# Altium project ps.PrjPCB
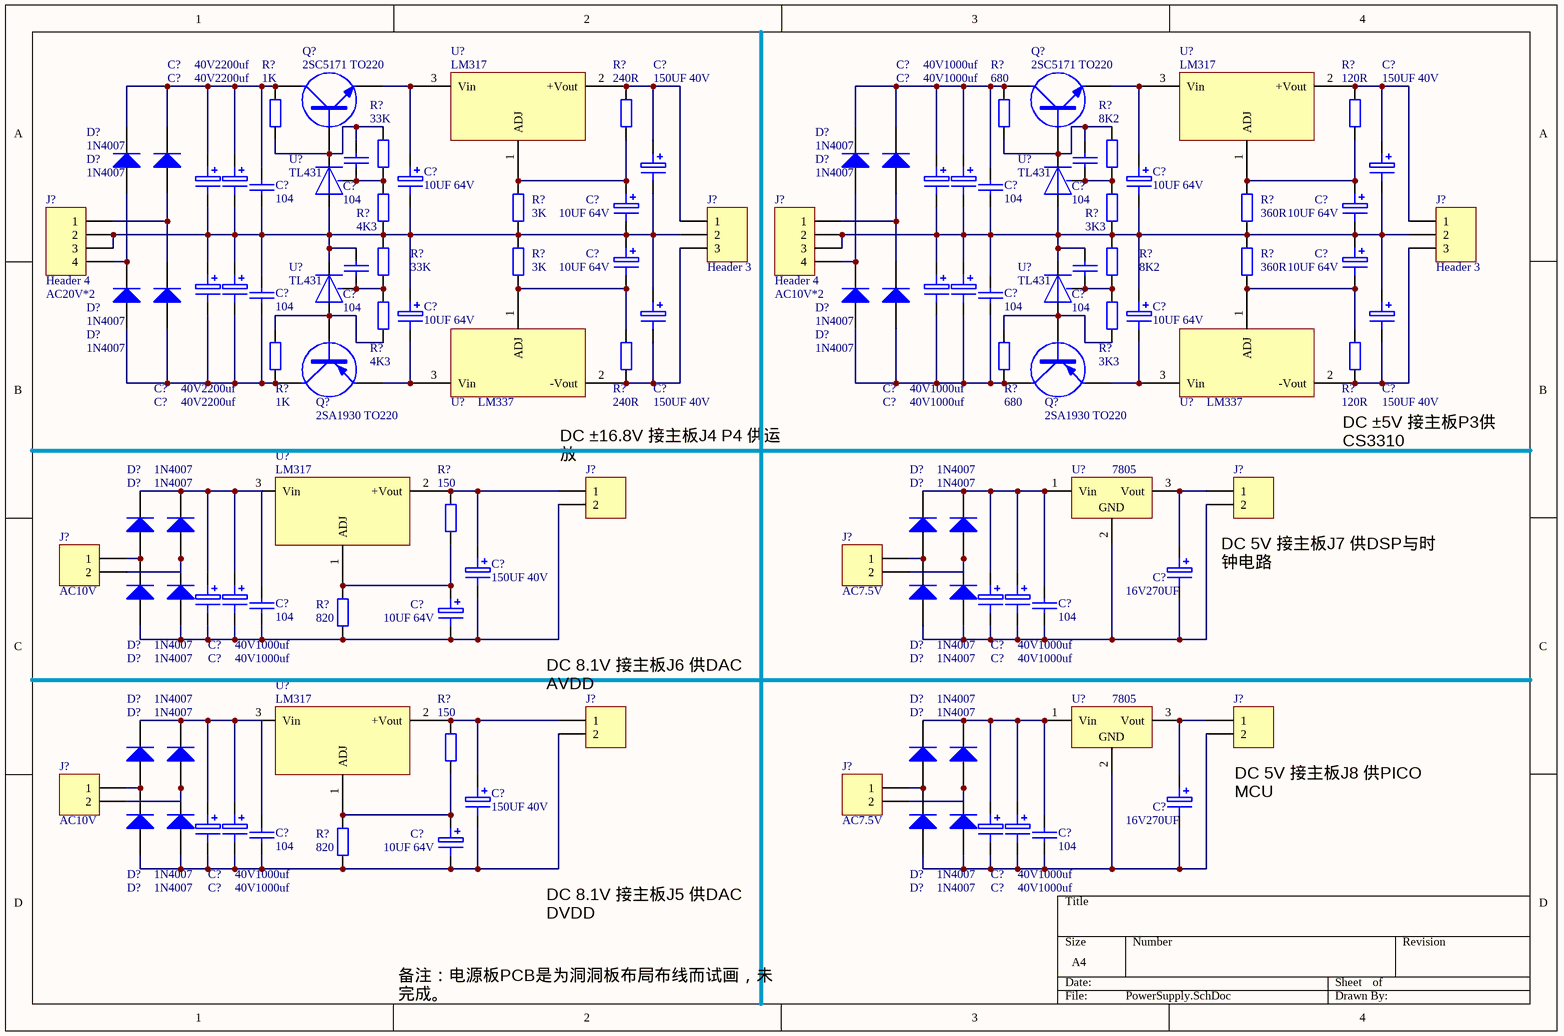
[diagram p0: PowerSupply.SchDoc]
1 sheet, 122 parts. Net scope: global (net labels, ports and power ports of the same name join across sheets).
Board file: ps.PcbDoc

## Sheet PowerSupply.SchDoc
size A4

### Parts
(Parts that share a designator on the sheet are numbered #1, #2 ... from top to bottom, then left to right.)
C1  104  [RAD0.2C]
C2  150UF 40V  [PEG124_D]
C3  40V2200uf  [PEG124_J]
C4  40V2200uf  [PEG124_J]
C5  10UF 64V  [PEG124_A]
C6  104  [RAD0.2C]
C7  10UF 64V  [PEG124_A]
C8  10UF 64V  [PEG124_A]
C9  104  [RAD0.2C]
C10  40V2200uf  [PEG124_J]
C11  40V2200uf  [PEG124_J]
C12  104  [RAD0.2C]
C13  10UF 64V  [PEG124_A]
C14  150UF 40V  [PEG124_D]
C18  150UF 40V  [RB.2/.4s]
C19  40V1000uf  [PEG124_S.7]
C20  104  [RAD0.2C]
C21  10UF 64V  [RB.1/.2C]
C?#1  104  [RAD0.2C]
C?#2  150UF 40V  [PEG124_D]
C?#3  40V1000uf  [PEG124_J]
C?#4  40V1000uf  [PEG124_J]
C?#5  10UF 64V  [PEG124_A]
C?#6  104  [RAD0.2C]
C?#7  10UF 64V  [PEG124_A]
C?#8  10UF 64V  [PEG124_A]
C?#9  40V1000uf  [PEG124_J]
C?#10  40V1000uf  [PEG124_J]
C?#11  104  [RAD0.2C]
C?#12  104  [RAD0.2C]
C?#13  10UF 64V  [PEG124_A]
C?#14  150UF 40V  [PEG124_D]
C?#15  16V270UF  [RB.2/.4s]
C?#16  40V1000uf  [PEG124_S.7]
C?#17  40V1000uf  [PEG124_S.7]
C?#18  40V1000uf  [PEG124_S.7]
C?#19  104  [RAD0.2C]
C?#20  150UF 40V  [RB.2/.4s]
C?#21  16V270UF  [RB.2/.4s]
C?#22  40V1000uf  [PEG124_S.7]
C?#23  40V1000uf  [PEG124_S.7]
C?#24  40V1000uf  [PEG124_S.7]
C?#25  40V1000uf  [PEG124_S.7]
C?#26  104  [RAD0.2C]
C?#27  10UF 64V  [RB.1/.2C]
C?#28  104  [RAD0.2C]
D1  1N4007  [DO-41]
D2  1N4007  [DO-41]
D3  1N4007  [DO-41]
D4  1N4007  [DO-41]
D9  1N4007  [DO-41]
D10  1N4007  [DO-41]
D11  1N4007  [DO-41]
D12  1N4007  [DO-41]
D?#1  1N4007  [DO-41]
D?#2  1N4007  [DO-41]
D?#3  1N4007  [DO-41]
D?#4  1N4007  [DO-41]
D?#5  1N4007  [DO-41]
D?#6  1N4007  [DO-41]
D?#7  1N4007  [DO-41]
D?#8  1N4007  [DO-41]
D?#9  1N4007  [DO-41]
D?#10  1N4007  [DO-41]
D?#11  1N4007  [DO-41]
D?#12  1N4007  [DO-41]
D?#13  1N4007  [DO-41]
D?#14  1N4007  [DO-41]
D?#15  1N4007  [DO-41]
D?#16  1N4007  [DO-41]
J1  Header 4  [HDR1X4]
J2  Header 3  [HDR1X3]
J5  (no value)  [SIP2C]
J6  (no value)  [SIP2C]
J?#1  Header 4  [HDR1X4]
J?#2  Header 3  [HDR1X3]
J?#3  (no value)  [SIP2C]
J?#4  (no value)  [SIP2C]
J?#5  (no value)  [SIP2C]
J?#6  (no value)  [SIP2C]
J?#7  (no value)  [SIP2C]
J?#8  (no value)  [SIP2C]
Q1  2SC5171 TO220  [TO-220S]
Q2  2SA1930 TO220  [TO-220s]
Q?#1  2SC5171 TO220  [TO-220S]
Q?#2  2SA1930 TO220  [TO-220s]
R1  1K  [AXIAL-0.4]
R2  240R  [AXIAL-0.4]
R3  33K  [AXIAL-0.4]
R4  4K3  [AXIAL-0.4]
R5  3K  [AXIAL-0.4]
R6  33K  [AXIAL-0.4]
R7  3K  [AXIAL-0.4]
R8  1K  [AXIAL-0.4]
R9  4K3  [AXIAL-0.4]
R10  240R  [AXIAL-0.4]
R11  150  [AXIAL-0.4]
R12  820  [AXIAL-0.4]
R?#1  680  [AXIAL-0.4]
R?#2  120R  [AXIAL-0.4]
R?#3  8K2  [AXIAL-0.4]
R?#4  3K3  [AXIAL-0.4]
R?#5  360R  [AXIAL-0.4]
R?#6  8K2  [AXIAL-0.4]
R?#7  360R  [AXIAL-0.4]
R?#8  3K3  [AXIAL-0.4]
R?#9  680  [AXIAL-0.4]
R?#10  120R  [AXIAL-0.4]
R?#11  150  [AXIAL-0.4]
R?#12  820  [AXIAL-0.4]
U1  LM317  [TO-220s]
U2  TL431  [to-92c]
U3  TL431  [to-92c]
U4  LM337  [TO-220s]
U6  LM317  [TO-220sh]
U?#1  LM317  [TO-220s]
U?#2  TL431  [to-92c]
U?#3  TL431  [to-92c]
U?#4  LM337  [TO-220s]
U?#5  7805  [TO-220s]
U?#6  LM317  [TO-220sh]
U?#7  7805  [TO-220s]

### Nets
NetC1_1: C1.1 Q1.1(B) R1.1 R3.1 U2.3(K)
NetC1_2: C1.2 R3.2 R4.2 U2.1(REF)
NetC2_1: C2.1 J2.1 R2.2 U1.2(+Vout)
NetC2_2: C2.2 C3.2 C4.2 C5.2 C6.2 C7.2 C8.1 C9.2 C10.1 C11.1 C12.1 C13.1 C14.1 J1.2 J1.3 J2.2 R4.1 R5.1 R6.2 R7.2 U2.2(A) U3.3(K)
NetC3_1: C3.1 C4.1 C6.1 D1.2(K) D2.2(K) Q1.2(C) R1.2
NetC5_1: C5.1 Q1.3(E) U1.3(Vin)
NetC7_1: C7.1 R2.1 R5.2 U1.1(ADJ)
NetC8_2: C8.2 R7.1 R10.2 U4.1(ADJ)
NetC9_1: C9.1 R6.1 R9.2 U3.1(REF)
NetC10_2: C10.2 C11.2 C12.2 D3.1(A) D4.1(A) Q2.3(C) R8.1
NetC13_2: C13.2 Q2.2(E) U4.3(Vin)
NetC14_2: C14.2 J2.3 R10.1 U4.2(-Vout)
NetC18_1: C18.1 J5.1 R11.2 U6.2(+Vout)
NetC18_2: C18.2 C19.2 C20.2 C21.2 C?#16.2 D11.1(A) D12.1(A) J5.2 R12.1
NetC19_1: C19.1 C20.1 C?#16.1 D9.2(K) D10.2(K) U6.3(Vin)
NetC21_1: C21.1 R11.1 R12.2 U6.1(ADJ)
NetC?#1_1: C?#1.1 Q?#1.1(B) R?#1.1 R?#3.1 U?#2.3(K)
NetC?#1_2: C?#1.2 R?#3.2 R?#4.2 U?#2.1(REF)
NetC?#2_1: C?#2.1 J?#2.1 R?#2.2 U?#1.2(+Vout)
NetC?#2_2: C?#2.2 C?#3.2 C?#4.2 C?#5.2 C?#6.2 C?#7.2 C?#8.1 C?#9.1 C?#10.1 C?#11.2 C?#12.1 C?#13.1 C?#14.1 J?#1.2 J?#1.3 J?#2.2 R?#4.1 R?#5.1 R?#6.2 R?#7.2 U?#2.2(A) U?#3.3(K)
NetC?#3_1: C?#3.1 C?#4.1 C?#6.1 D?#1.2(K) D?#2.2(K) Q?#1.2(C) R?#1.2
NetC?#5_1: C?#5.1 Q?#1.3(E) U?#1.3(Vin)
NetC?#7_1: C?#7.1 R?#2.1 R?#5.2 U?#1.1(ADJ)
NetC?#8_2: C?#8.2 R?#7.1 R?#10.2 U?#4.1(ADJ)
NetC?#9_2: C?#9.2 C?#10.2 C?#12.2 D?#3.1(A) D?#4.1(A) Q?#2.3(C) R?#9.1
NetC?#11_1: C?#11.1 R?#6.1 R?#8.2 U?#3.1(REF)
NetC?#13_2: C?#13.2 Q?#2.2(E) U?#4.3(Vin)
NetC?#14_2: C?#14.2 J?#2.3 R?#10.1 U?#4.2(-Vout)
NetC?#15_1: C?#15.1 J?#3.1 U?#5.3(Vout)
NetC?#15_2: C?#15.2 C?#17.2 C?#18.2 C?#19.2 D?#7.1(A) D?#8.1(A) J?#3.2 U?#5.2(GND)
NetC?#17_1: C?#17.1 C?#18.1 C?#19.1 D?#5.2(K) D?#6.2(K) U?#5.1(Vin)
NetC?#20_1: C?#20.1 J?#5.1 R?#11.2 U?#6.2(+Vout)
NetC?#20_2: C?#20.2 C?#22.2 C?#23.2 C?#26.2 C?#27.2 D?#13.1(A) D?#14.1(A) J?#5.2 R?#12.1
NetC?#21_1: C?#21.1 J?#6.1 U?#7.3(Vout)
NetC?#21_2: C?#21.2 C?#24.2 C?#25.2 C?#28.2 D?#15.1(A) D?#16.1(A) J?#6.2 U?#7.2(GND)
NetC?#22_1: C?#22.1 C?#23.1 C?#26.1 D?#9.2(K) D?#10.2(K) U?#6.3(Vin)
NetC?#24_1: C?#24.1 C?#25.1 C?#28.1 D?#11.2(K) D?#12.2(K) U?#7.1(Vin)
NetC?#27_1: C?#27.1 R?#11.1 R?#12.2 U?#6.1(ADJ)
NetD1_1: D1.1(A) D3.2(K) J1.4
NetD2_1: D2.1(A) D4.2(K) J1.1
NetD9_1: D9.1(A) D11.2(K) J6.1
NetD10_1: D10.1(A) D12.2(K) J6.2
NetD?#1_1: D?#1.1(A) D?#3.2(K) J?#1.4
NetD?#2_1: D?#2.1(A) D?#4.2(K) J?#1.1
NetD?#5_1: D?#5.1(A) D?#7.2(K) J?#4.1
NetD?#6_1: D?#6.1(A) D?#8.2(K) J?#4.2
NetD?#9_1: D?#9.1(A) D?#13.2(K) J?#7.1
NetD?#10_1: D?#10.1(A) D?#14.2(K) J?#7.2
NetD?#11_1: D?#11.1(A) D?#15.2(K) J?#8.1
NetD?#12_1: D?#12.1(A) D?#16.2(K) J?#8.2
NetQ2_1: Q2.1(B) R8.2 R9.1 U3.2(A)
NetQ?#2_1: Q?#2.1(B) R?#8.1 R?#9.2 U?#3.2(A)

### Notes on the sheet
- AC20V*2
- AC10V*2
- (near J5) DC ±16.8V 接主板J4 P4 供运放
- DC ±5V 接主板P3供CS3310
  P3 接3 4 5脚即可
- DC 5V 接主板J7 供DSP与时钟电路
- (near J6) AC10V
- (near J?#4) AC7.5V
- (near J?#5) DC 8.1V 接主板J6 供DAC AVDD
- (near J?#7) AC10V
- (near J?#8) AC7.5V
- (near J?#6) DC 5V 接主板J8 供PICO MCU
- DC 8.1V 接主板J5 供DAC DVDD
- 备注：电源板PCB是为洞洞板布局布线而试画，未完成。

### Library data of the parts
C1 C6 C9 C12 C20 C?#1 C?#6 C?#11 C?#12 C?#19 C?#26 C?#28 = CAP: Capacitor
C2-C5 C7 C8 C10 C11 C13 C14 C18 C19 C21 C?#2-C?#5 C?#7-C?#10 C?#13-C?#18 C?#20-C?#25 C?#27 = ELECTRO1: Electrolytic Capacitor
D1-D4 D9-D12 D?#1-D?#16 = Diode 1N4007: 1 Amp General Purpose Rectifier
J1 J?#1 = Header 4: Header, 4-Pin
J2 J?#2 = Header 3: Header, 3-Pin
J5 J6 J?#3-J?#8 = Header 2: Header, 2-Pin
Q1 Q?#1 = NPN: NPN Transistor
Q2 Q?#2 = PNP: PNP Transistor; pin to pad: 2>3 3>2
R1 R8 = Res2: Resistor
R2-R7 R9-R12 R?#1-R?#12 = Res2: Resistor; Value: 1K
U1 U6 U?#1 U?#6 = LM217
U4 U?#4 = LM137H: pin to pad: 2>3 3>2
U?#5 U?#7 = 78XX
